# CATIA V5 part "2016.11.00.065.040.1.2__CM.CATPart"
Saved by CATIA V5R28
Part number: 2016.11.00.065.040.1.2__CM
Property "id_number": "2016.11.00.065.040.1.2"
Publications: "Absolute Axis System", "driver", "slider", "base", "cam diagram"
Bounding box of the stored display mesh (mm): x -40 to 145, y -65 to 65, z 0 to 200
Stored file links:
  N:\B2\Normteile\K\2016\11-14\006\cm\2016.11.00.065.040.1.2__CM.CATPart
  H:\CAD_Startmodelle\Tests\fill-in_PRT-SL_TEMPLATE.xlsx
  H:\CAD_Startmodelle\V5-R24\R24_TEMPLATE_PRT_FIBRO_CAM_TECNOLOGIES_INDEX.xlsx
  H:\z_Einordnen\170511__Anfrage_TK_HN\170511__CC01_TKHN.CATPart
  N:\B2\Normteile\K\2016\9xxx\2016.9024.1705.001\Entwurf_\170511__CC01_TKHN.CATPart
  N:\B2\Normteile\K\2016\9xxx\2016.9024.1707.006\Konstruktion\2016.9024.1707.006__HP__CUSTOMIZED_CAM_CM.CATPart
  N:\B2\Normteile\K\2016\9xxx\2016.9024.1707.005\Konstruktion\2016.9024.1707.005__HP__CUSTOMIZED_CAM_CM.CATPart
  N:\B2\Normteile\K\2016\9xxx\2016.9024.1707.008\Konstruktion\2016.9024.1707.008__HP__CUSTOMIZED_CAM_CM.CATPart
  N:\B2\Normteile\K\2016\9xxx\2016.9024.1707.009\Konstruktion\2016.9024.1707.009__HP__CUSTOMIZED_CAM_CM.CATPart
  N:\B2\Normteile\K\2016\9xxx\2016.9024.1707.010\Konstruktion\2016.9024.1707.010__HP__CUSTOMIZED_CAM_CM.CATPart
  N:\B2\Normteile\K\2016\9xxx\2016.9024.1708.002\Konstruktion\2016.9024.1708.002__HP__CUSTOMIZED_CAM_CM.CATPart
  N:\B2\Normteile\K\2016\9xxx\2016.9024.1802.001\Konstruktion\2016.9024.1802.001__HP__CUSTOMIZED_CAM_CM.CATPart
  N:\B2\Normteile\K\2016\9xxx\2016.9024.1802.002\Konstruktion\2016.9024.1802.002__HP__CUSTOMIZED_CAM_CM.CATPart
  N:\B2\Normteile\K\2016\9xxx\2016.9024.1811.003\Konstruktion\2016.9024.1811.003__HP__CUSTOMIZED_CAM_CM.CATPart
  N:\B2\Normteile\K\2016\9xxx\2016.9015.1811.001\Konstruktion\am\2016.9015.1811.001__AM__FCC_HV_DMC_0125-00.CATPart
  N:\B2\Normteile\K\2016\9xxx\2016.9024.1811.009\Konstruktion\2016.9024.1811.009__HP__CUSTOMIZED_CAM_CM.CATPart
  N:\B2\Normteile\K\2016\9xxx\2016.9024.1911.002\Konstruktion\am\2016.9024.1911.002__AM__CUSTOMIZED_CAM_CM.CATPart
  N:\B2\Normteile\K\2016\9xxx\2016.9024.2002.006\Konstruktion\2016.9024.2002.006__AM.CATPart
  N:\B2\Normteile\K\2016\9xxx\2016.9024.2004.001\Konstruktion\2016.9024.2004.001__AM__FCC_HV_CAEC_0260-45.CATPart
  N:\B2\Normteile\K\2016\9xxx\2016.9024.2006.002\Konstruktion\2016.9024.2006.002__AM__FCC_HV_CAEC_0260-40.CATPart
  N:\B2\Normteile\K\2016\9xxx\2016.9024.2006.005\Konstruktion\am\2016.9024.2006.005__AM__CFCC_HV_AEPC_0080-65.CATPart
  N:\B2\Normteile\K\2016\9xxx\2016.9024.2006.004\Konstruktion\am\2016.9024.2006.004__AM__CFCC_HV_AEC_0210-35.CATPart
  N:\B2\Normteile\K\2016\9xxx\2016.9026.2006.001\Konstruktion\am\2016.9026.2006.001__AM__FCC_LV_CAEC_0180-40.CATPart
  N:\B2\Normteile\K\2016\9xxx\2016.9015.2007.001\Konstruktion\am\2016.9015.2007.001__AM__FCC_HV_CDMPC_0090-00.CATPart
  N:\B2\Normteile\K\2016\9xxx\2016.9024.2005.001\Konstruktion\am\2016.9024.2005.001__AM__CFCC_HV_AEPC_1400-70.CATPart
  N:\B2\Normteile\K\2016\9xxx\2016.9024.2007.004\Konstruktion\am\2016.9024.2007.004__AM__CFCC_HV_AEC_1250-80.CATPart
  N:\B2\Normteile\K\2016\11-14\005\2016.11.00.052.040.1.02__AS__DIE_MOUNT_CAM__W52_A0_S40.CATProduct
  N:\B2\Normteile\K\2016\11-14\cm\005\catia\2016.11.00.052.025.1.2__CM.CATPart
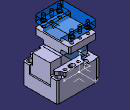
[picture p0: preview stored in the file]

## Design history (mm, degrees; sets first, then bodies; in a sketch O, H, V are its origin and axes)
Parameters
  group "process_parameters"
    modeltype = ""
    stocklist = ""
    id_number = "2016.11.00.065.040.1.2"
    id_number_rough_part = ""
    revision_index = ""
    revision_date = ""
    revision_description = ""
    category = ""
    material = ""
    manufacturing_information = ""
    standard = ""
  group "release_parameters_startmodel"
    sm_revision_index = "2016_00" {design table}
    sm_revision_date = "20.08.2016" {design table}
    sm_revision_name = "Meyer" {design table}
    sm_revision_description = "new part template FIBRO cam tecnologies" {design table}
AxisSystem1: origin (0, 0, 0), X (1, 0, 0), Y (0, 1, 0), Z (0, 0, 1)
Set1 "reference elements"
  Sketch1 "cam diagram" on ZX plane of AxisSystem1, origin (0, 0, 0), H (-1, 0, 0), V (0, 0, 1)
    line L1 (0, 0) -> (40, 0)
    line L2 (40, 0) -> (0, 40)
    point P2 (0, 40)
    line L3 (0, 40) -> (0, 0)
    length L1 = 40
    angle H L2 = 45
    horizontal: L1 H
    coincidence: P2 V
    vertical: L3 V
Body1 "finished_part" (main body)
  Body2 "rough_part"
  Add1 "rough_part": tool Body2
  Body3 "milling operations"
  Remove1 "milling operations": tool Body3
  Body4 "drilling operations"
  Remove2 "drilling operations": tool Body4
Body5 "driver"
  Solid1: solid without history
Body6 "slider"
  Solid2: solid without history
Body7 "base"
  Solid3: solid without history
Body8 "opened position"
  Body9 "slider"
    Body10 "slider"
      Solid4: linked copy from another document
    Assemble1: tool Body10
    Translate1: FirstPoint vertex [element of Sketch1 | element of Sketch1], SecondPoint vertex [element of Sketch1 | element of Sketch1], ToTransfor Assemble1
  Assemble2: tool Body9
  Body11 "driver"
    Body12 "driver"
      Solid5: linked copy from another document
    Assemble3: tool Body12
    Translate2: FirstPoint vertex [element of Sketch1 | element of Sketch1], SecondPoint vertex [element of Sketch1 | element of Sketch1], ToTransfor Assemble3
  Assemble4: tool Body11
